// Mitsubishi GX Works2 project: L02_EIP_LIBRARY   PLC: FX3G

// task Task_01 (event TRUE, interval 0, priority 31): POU_01
// user libraries (not included): BIT_TO_INT

PROGRAM POU_01
VAR
  FB_EIP_MASTER_1 : FB_EIP_MASTER;
  FB_EIP_MASTER_2 : FB_EIP_MASTER;
  FB_EIP_MASTER_3 : FB_EIP_MASTER;
  IN_OUT_EIP_SLAVE1_1 : IN_OUT_EIP_SLAVE1;
  var1 : INT;
  vare : INT;
  BITR : BOOL;
  BITR1 : BOOL;
  BEW : BOOL;
  WE : BOOL;
  IN_OUT_EIP_SLAVE1_2 : IN_OUT_EIP_SLAVE1;
  IN_OUT_EIP_SLAVE2_1 : IN_OUT_EIP_SLAVE2;
END_VAR
(* structured ladder/FBD written out as ST: instructions are called as NAME(EN, inputs, outputs); _pN, _eN, _tN stand for wires *)
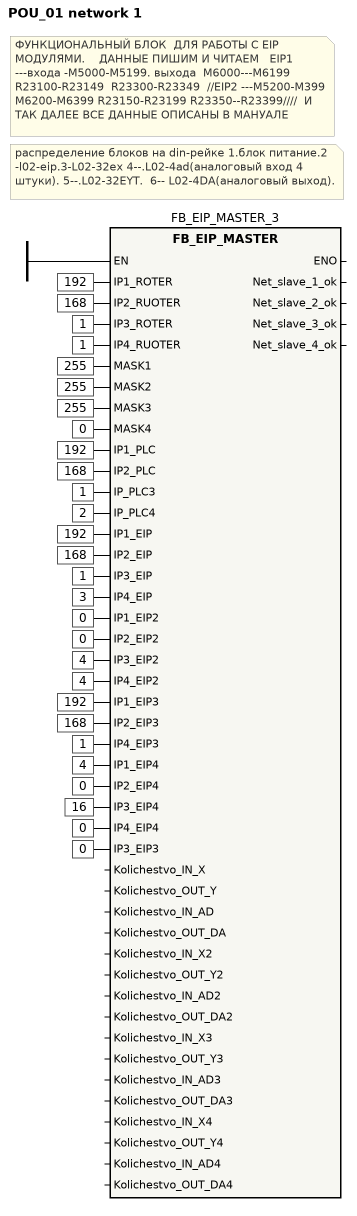
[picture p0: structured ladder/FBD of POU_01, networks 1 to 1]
(* network 1 *)
(* ФУНКЦИОНАЛЬНЫЙ БЛОК  ДЛЯ РАБОТЫ С EIP МОДУЛЯМИ.    ДАННЫЕ ПИШИМ И ЧИТАЕМ   EIP1 ---входа -М5000-М5199. выхода  M6000---M6199  R23100-R23149  R23300-R23349  //EIP2 ---M5200-M399  M6200-M6399 R23150-R23199 R23350--R23399////  И ТАК ДАЛЕЕ ВСЕ ДАННЫЕ ОПИСАНЫ В МАНУАЛЕ *)
(* распределение блоков на din-рейке 1.блок питание.2 -l02-eip.3-L02-32ex 4--.L02-4ad(аналоговый вход 4 штуки). 5--.L02-32EYT.  6-- L02-4DA(аналоговый выход). *)
FB_EIP_MASTER_3(EN := TRUE, IP1_ROTER := 192, IP2_RUOTER := 168, IP3_ROTER := 1, IP4_RUOTER := 1, MASK1 := 255, MASK2 := 255, MASK3 := 255, MASK4 := 0, IP1_PLC := 192, IP2_PLC := 168, IP_PLC3 := 1, IP_PLC4 := 2, IP1_EIP := 192, IP2_EIP := 168, IP3_EIP := 1, IP4_EIP := 3, IP1_EIP2 := 0, IP2_EIP2 := 0, IP3_EIP2 := 4, IP4_EIP2 := 4, IP1_EIP3 := 192, IP2_EIP3 := 168, IP4_EIP3 := 1, IP1_EIP4 := 4, IP2_EIP4 := 0, IP3_EIP4 := 16, IP4_EIP4 := 0, IP3_EIP3 := 0);
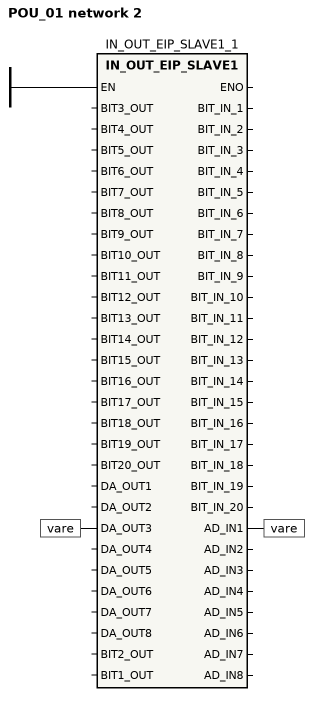
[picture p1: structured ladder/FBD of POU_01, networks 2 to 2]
(* network 2 *)
IN_OUT_EIP_SLAVE1_1(EN := TRUE, DA_OUT3 := vare, AD_IN1 => vare);
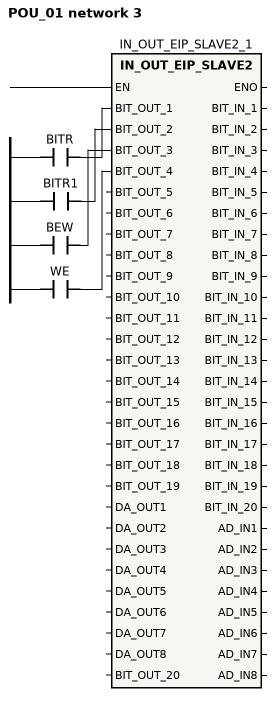
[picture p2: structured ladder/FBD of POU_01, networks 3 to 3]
(* network 3 *)
IN_OUT_EIP_SLAVE2_1(EN := TRUE, BIT_OUT_1 := BITR, BIT_OUT_2 := BITR1, BIT_OUT_3 := BEW, BIT_OUT_4 := WE);
END_PROGRAM

FUNCTION_BLOCK FB_EIP_MASTER
VAR_INPUT
  IP1_ROTER : INT;
  IP2_RUOTER : INT;
  IP3_ROTER : INT;
  IP4_RUOTER : INT;
  MASK1 : INT;
  MASK2 : INT;
  MASK3 : INT;
  MASK4 : INT;
  IP1_PLC : INT;
  IP2_PLC : INT;
  IP_PLC3 : INT;
  IP_PLC4 : INT;
  IP1_EIP : INT;
  IP2_EIP : INT;
  IP3_EIP : INT;
  IP4_EIP : INT;
  IP1_EIP2 : INT;
  IP2_EIP2 : INT;
  IP3_EIP2 : INT;
  IP4_EIP2 : INT;
  IP1_EIP3 : INT;
  IP2_EIP3 : INT;
  IP4_EIP3 : INT;
  IP1_EIP4 : INT;
  IP2_EIP4 : INT;
  IP3_EIP4 : INT;
  IP4_EIP4 : INT;
  IP3_EIP3 : INT;
  Kolichestvo_IN_X : INT;
  Kolichestvo_OUT_Y : INT;
  Kolichestvo_IN_AD : INT;
  Kolichestvo_OUT_DA : INT;
  Kolichestvo_IN_X2 : INT;
  Kolichestvo_OUT_Y2 : INT;
  Kolichestvo_IN_AD2 : INT;
  Kolichestvo_OUT_DA2 : INT;
  Kolichestvo_IN_X3 : INT;
  Kolichestvo_OUT_Y3 : INT;
  Kolichestvo_IN_AD3 : INT;
  Kolichestvo_OUT_DA3 : INT;
  Kolichestvo_IN_X4 : INT;
  Kolichestvo_OUT_Y4 : INT;
  Kolichestvo_IN_AD4 : INT;
  Kolichestvo_OUT_DA4 : INT;
END_VAR
VAR_OUTPUT
  Net_slave_1_ok : BOOL;
  Net_slave_2_ok : BOOL;
  Net_slave_3_ok : BOOL;
  Net_slave_4_ok : BOOL;
END_VAR
(* structured ladder/FBD written out as ST: instructions are called as NAME(EN, inputs, outputs); _pN, _eN, _tN stand for wires *)
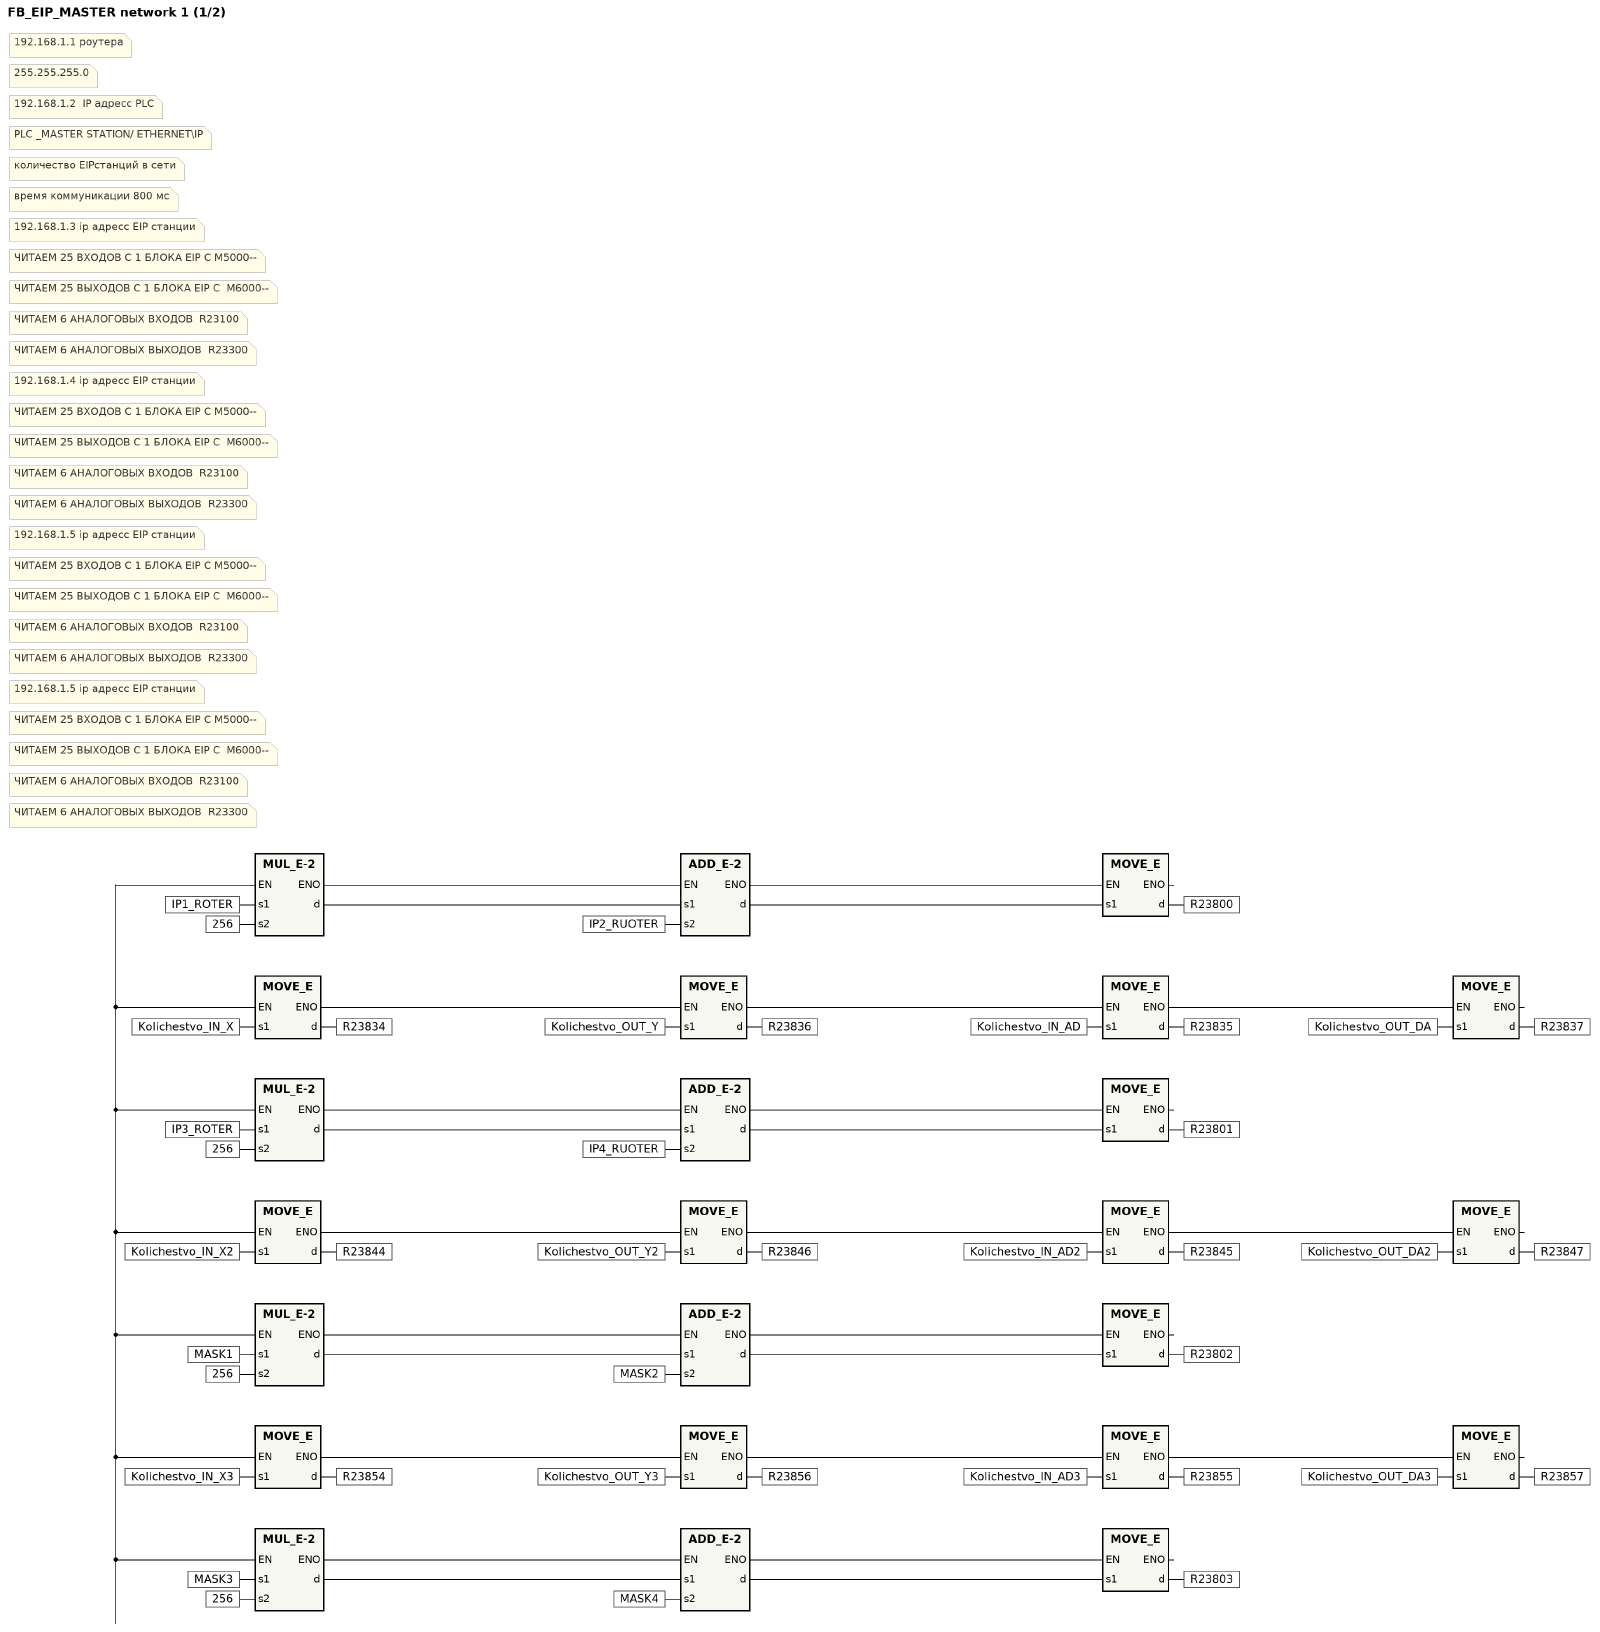
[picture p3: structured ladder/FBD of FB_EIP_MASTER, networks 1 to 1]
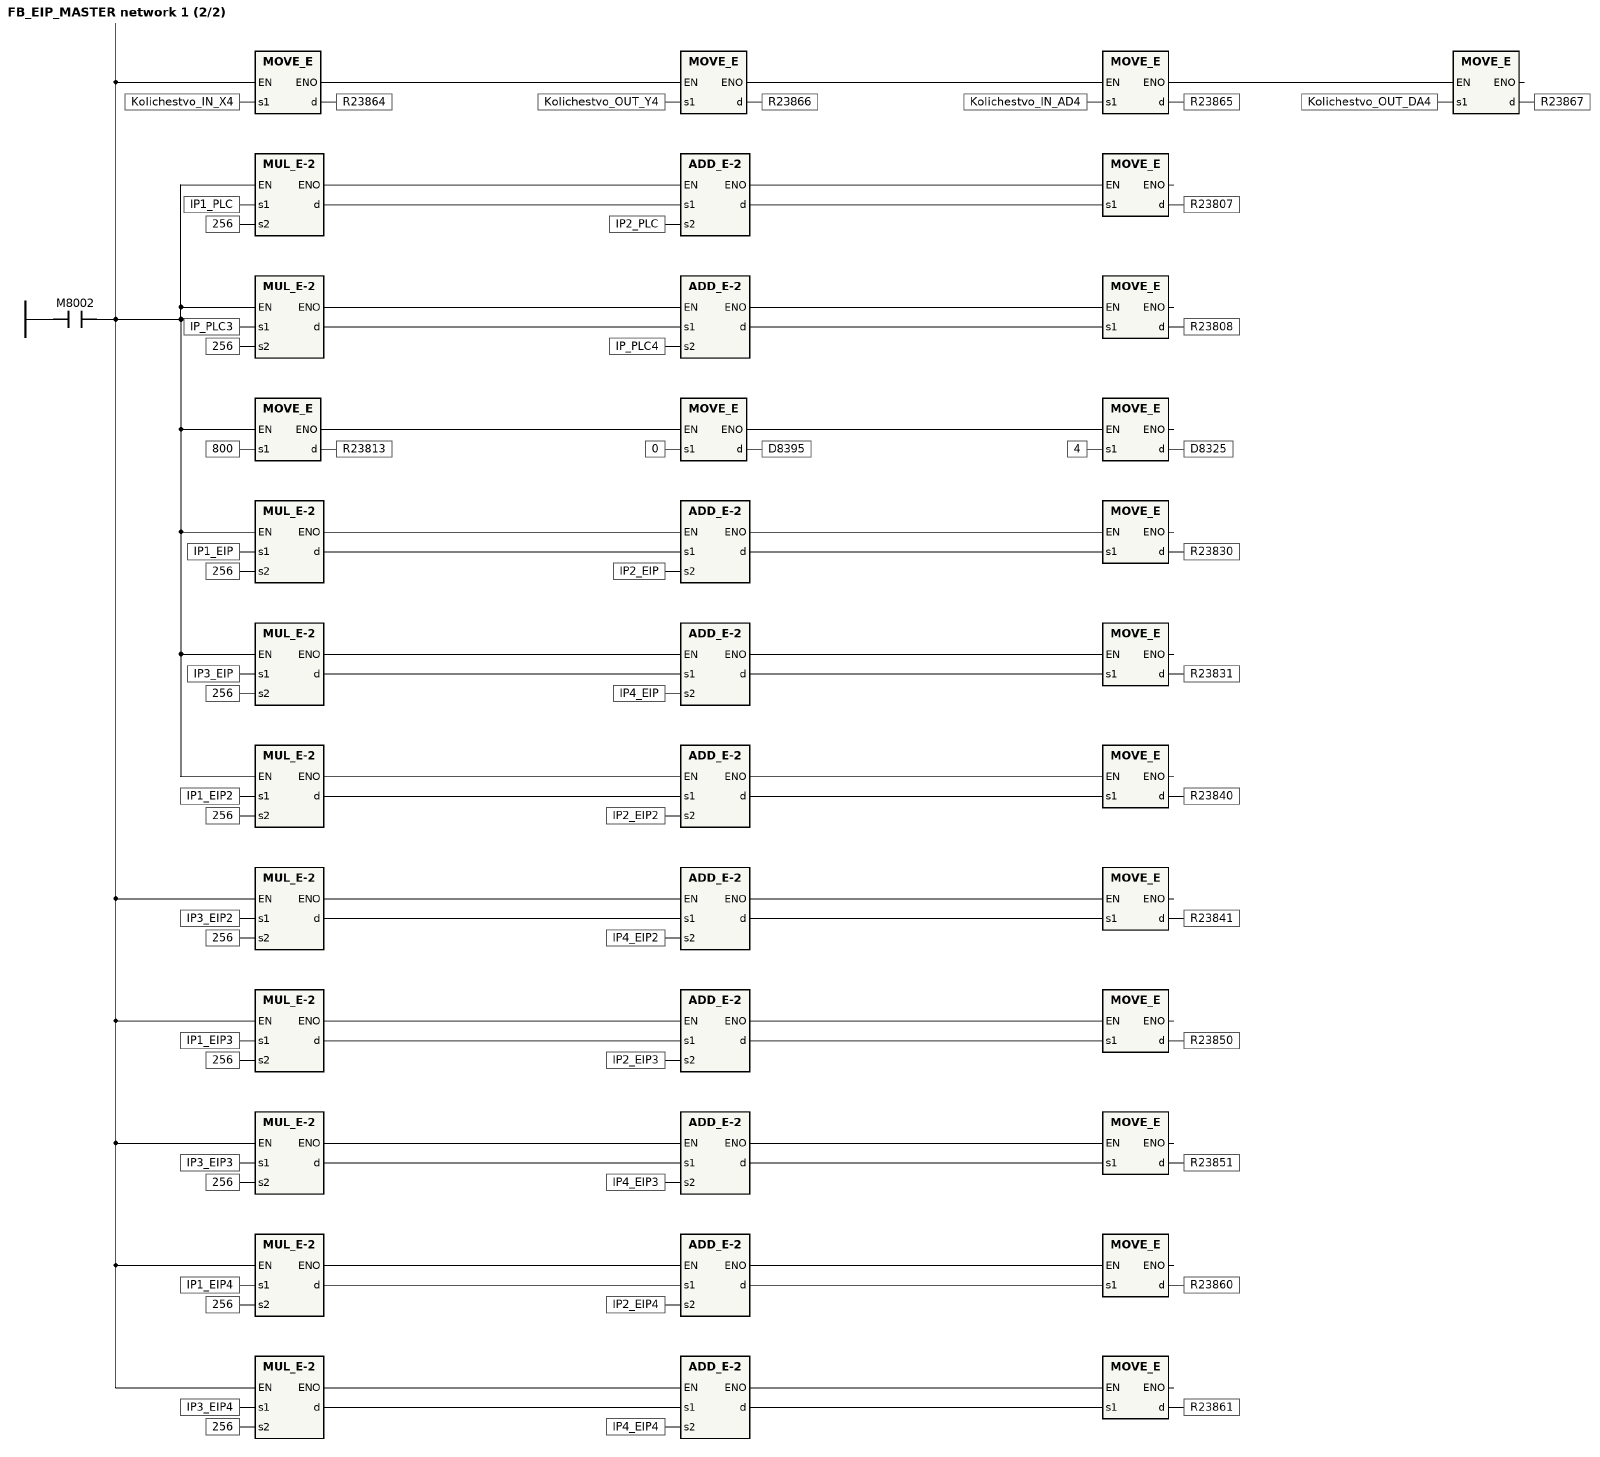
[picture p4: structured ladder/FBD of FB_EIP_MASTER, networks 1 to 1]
(* network 1 *)
(* 192.168.1.1 роутера *)
(* 255.255.255.0 *)
(* 192.168.1.2  IP адресс PLC *)
(* PLC _MASTER STATION/ ETHERNET\IP *)
(* количество EIPстанций в сети *)
(* время коммуникации 800 мс *)
(* 192.168.1.3 ip адресс EIP станции *)
(* ЧИТАЕМ 25 ВХОДОВ С 1 БЛОКА EIP C M5000-- *)
(* ЧИТАЕМ 25 ВЫХОДОВ С 1 БЛОКА EIP C  M6000-- *)
(* ЧИТАЕМ 6 АНАЛОГОВЫХ ВХОДОВ  R23100 *)
(* ЧИТАЕМ 6 АНАЛОГОВЫХ ВЫХОДОВ  R23300 *)
(* 192.168.1.4 ip адресс EIP станции *)
(* ЧИТАЕМ 25 ВХОДОВ С 1 БЛОКА EIP C M5000-- *)
(* ЧИТАЕМ 25 ВЫХОДОВ С 1 БЛОКА EIP C  M6000-- *)
(* ЧИТАЕМ 6 АНАЛОГОВЫХ ВХОДОВ  R23100 *)
(* ЧИТАЕМ 6 АНАЛОГОВЫХ ВЫХОДОВ  R23300 *)
(* 192.168.1.5 ip адресс EIP станции *)
(* ЧИТАЕМ 25 ВХОДОВ С 1 БЛОКА EIP C M5000-- *)
(* ЧИТАЕМ 25 ВЫХОДОВ С 1 БЛОКА EIP C  M6000-- *)
(* ЧИТАЕМ 6 АНАЛОГОВЫХ ВХОДОВ  R23100 *)
(* ЧИТАЕМ 6 АНАЛОГОВЫХ ВЫХОДОВ  R23300 *)
(* 192.168.1.5 ip адресс EIP станции *)
(* ЧИТАЕМ 25 ВХОДОВ С 1 БЛОКА EIP C M5000-- *)
(* ЧИТАЕМ 25 ВЫХОДОВ С 1 БЛОКА EIP C  M6000-- *)
(* ЧИТАЕМ 6 АНАЛОГОВЫХ ВХОДОВ  R23100 *)
(* ЧИТАЕМ 6 АНАЛОГОВЫХ ВЫХОДОВ  R23300 *)
_e2 := MUL_E(M8002, IP1_ROTER, 256, _t1);
_e4 := ADD_E(_e2, _t1, IP2_RUOTER, _t3);
MOVE_E(_e4, _t3, R23800);
_e6 := MUL_E(M8002, IP3_ROTER, 256, _t5);
_e8 := ADD_E(_e6, _t5, IP4_RUOTER, _t7);
MOVE_E(_e8, _t7, R23801);
_e10 := MUL_E(M8002, MASK1, 256, _t9);
_e12 := ADD_E(_e10, _t9, MASK2, _t11);
MOVE_E(_e12, _t11, R23802);
_e14 := MUL_E(M8002, MASK3, 256, _t13);
_e16 := ADD_E(_e14, _t13, MASK4, _t15);
MOVE_E(_e16, _t15, R23803);
_e18 := MUL_E(M8002, IP1_PLC, 256, _t17);
_e20 := ADD_E(_e18, _t17, IP2_PLC, _t19);
MOVE_E(_e20, _t19, R23807);
_e22 := MUL_E(M8002, IP_PLC3, 256, _t21);
_e24 := ADD_E(_e22, _t21, IP_PLC4, _t23);
MOVE_E(_e24, _t23, R23808);
_e25 := MOVE_E(M8002, 800, R23813);
_e26 := MOVE_E(_e25, 0, D8395);
MOVE_E(_e26, 4, D8325);
_e28 := MUL_E(M8002, IP1_EIP, 256, _t27);
_e30 := ADD_E(_e28, _t27, IP2_EIP, _t29);
MOVE_E(_e30, _t29, R23830);
_e32 := MUL_E(M8002, IP3_EIP, 256, _t31);
_e34 := ADD_E(_e32, _t31, IP4_EIP, _t33);
MOVE_E(_e34, _t33, R23831);
_e35 := MOVE_E(M8002, Kolichestvo_IN_X, R23834);
_e36 := MOVE_E(_e35, Kolichestvo_OUT_Y, R23836);
_e37 := MOVE_E(_e36, Kolichestvo_IN_AD, R23835);
MOVE_E(_e37, Kolichestvo_OUT_DA, R23837);
_e39 := MUL_E(M8002, IP1_EIP2, 256, _t38);
_e41 := ADD_E(_e39, _t38, IP2_EIP2, _t40);
MOVE_E(_e41, _t40, R23840);
_e43 := MUL_E(M8002, IP3_EIP2, 256, _t42);
_e45 := ADD_E(_e43, _t42, IP4_EIP2, _t44);
MOVE_E(_e45, _t44, R23841);
_e46 := MOVE_E(M8002, Kolichestvo_IN_X2, R23844);
_e47 := MOVE_E(_e46, Kolichestvo_OUT_Y2, R23846);
_e48 := MOVE_E(_e47, Kolichestvo_IN_AD2, R23845);
MOVE_E(_e48, Kolichestvo_OUT_DA2, R23847);
_e50 := MUL_E(M8002, IP1_EIP3, 256, _t49);
_e52 := ADD_E(_e50, _t49, IP2_EIP3, _t51);
MOVE_E(_e52, _t51, R23850);
_e54 := MUL_E(M8002, IP3_EIP3, 256, _t53);
_e56 := ADD_E(_e54, _t53, IP4_EIP3, _t55);
MOVE_E(_e56, _t55, R23851);
_e57 := MOVE_E(M8002, Kolichestvo_IN_X3, R23854);
_e58 := MOVE_E(_e57, Kolichestvo_OUT_Y3, R23856);
_e59 := MOVE_E(_e58, Kolichestvo_IN_AD3, R23855);
MOVE_E(_e59, Kolichestvo_OUT_DA3, R23857);
_e61 := MUL_E(M8002, IP1_EIP4, 256, _t60);
_e63 := ADD_E(_e61, _t60, IP2_EIP4, _t62);
MOVE_E(_e63, _t62, R23860);
_e65 := MUL_E(M8002, IP3_EIP4, 256, _t64);
_e67 := ADD_E(_e65, _t64, IP4_EIP4, _t66);
MOVE_E(_e67, _t66, R23861);
_e68 := MOVE_E(M8002, Kolichestvo_IN_X4, R23864);
_e69 := MOVE_E(_e68, Kolichestvo_OUT_Y4, R23866);
_e70 := MOVE_E(_e69, Kolichestvo_IN_AD4, R23865);
MOVE_E(_e70, Kolichestvo_OUT_DA4, R23867);
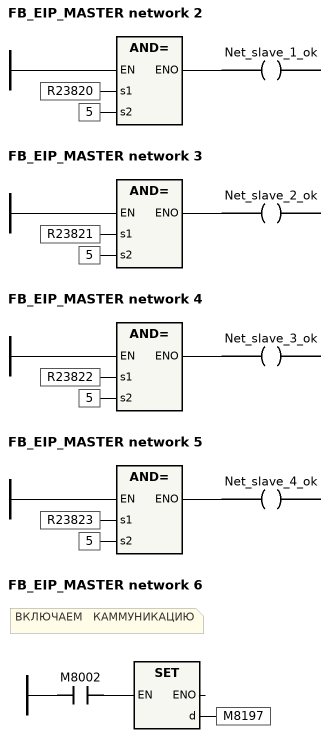
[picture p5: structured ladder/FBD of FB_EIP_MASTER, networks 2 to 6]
(* network 2 *)
_e1 := AND=(TRUE, R23820, 5);
Net_slave_1_ok := _e1;
(* network 3 *)
_e1 := AND=(TRUE, R23821, 5);
Net_slave_2_ok := _e1;
(* network 4 *)
_e1 := AND=(TRUE, R23822, 5);
Net_slave_3_ok := _e1;
(* network 5 *)
_e1 := AND=(TRUE, R23823, 5);
Net_slave_4_ok := _e1;
(* network 6 *)
(* ВКЛЮЧАЕМ   КАММУНИКАЦИЮ *)
SET(M8002, M8197);
END_FUNCTION_BLOCK

FUNCTION_BLOCK IN_OUT_EIP_SLAVE1
VAR_INPUT
  BIT3_OUT : BOOL;
  BIT4_OUT : BOOL;
  BIT5_OUT : BOOL;
  BIT6_OUT : BOOL;
  BIT7_OUT : BOOL;
  BIT8_OUT : BOOL;
  BIT9_OUT : BOOL;
  BIT10_OUT : BOOL;
  BIT11_OUT : BOOL;
  BIT12_OUT : BOOL;
  BIT13_OUT : BOOL;
  BIT14_OUT : BOOL;
  BIT15_OUT : BOOL;
  BIT16_OUT : BOOL;
  BIT17_OUT : BOOL;
  BIT18_OUT : BOOL;
  BIT19_OUT : BOOL;
  BIT20_OUT : BOOL;
END_VAR
VAR_OUTPUT
  BIT_IN_1 : BOOL;
  BIT_IN_2 : BOOL;
  BIT_IN_3 : BOOL;
  BIT_IN_4 : BOOL;
  BIT_IN_5 : BOOL;
  BIT_IN_6 : BOOL;
  BIT_IN_7 : BOOL;
  BIT_IN_8 : BOOL;
  BIT_IN_9 : BOOL;
  BIT_IN_10 : BOOL;
  BIT_IN_11 : BOOL;
  BIT_IN_12 : BOOL;
  BIT_IN_13 : BOOL;
  BIT_IN_14 : BOOL;
  BIT_IN_15 : BOOL;
  BIT_IN_16 : BOOL;
  BIT_IN_17 : BOOL;
  BIT_IN_18 : BOOL;
  BIT_IN_19 : BOOL;
  BIT_IN_20 : BOOL;
  AD_IN1 : INT;
  AD_IN2 : INT;
  AD_IN3 : INT;
  AD_IN4 : INT;
  AD_IN5 : INT;
  AD_IN6 : INT;
  AD_IN7 : INT;
  AD_IN8 : INT;
END_VAR
VAR_INPUT
  DA_OUT1 : INT;
  DA_OUT2 : INT;
  DA_OUT3 : INT;
  DA_OUT4 : INT;
  DA_OUT5 : INT;
  DA_OUT6 : INT;
  DA_OUT7 : INT;
  DA_OUT8 : INT;
  BIT2_OUT : BOOL;
  BIT1_OUT : BOOL;
END_VAR
(* structured ladder/FBD written out as ST: instructions are called as NAME(EN, inputs, outputs); _pN, _eN, _tN stand for wires *)
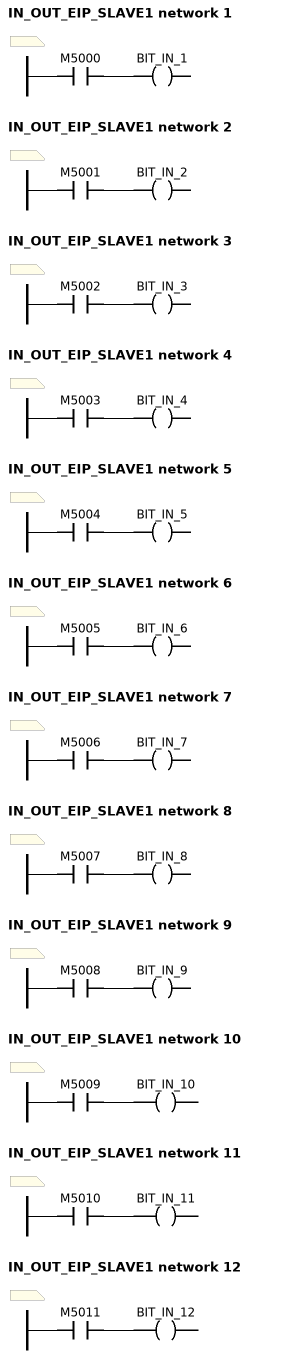
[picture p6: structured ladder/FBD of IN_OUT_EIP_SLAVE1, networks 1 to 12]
(* network 1 *)
(*  *)
BIT_IN_1 := M5000;
(* network 2 *)
(*  *)
BIT_IN_2 := M5001;
(* network 3 *)
(*  *)
BIT_IN_3 := M5002;
(* network 4 *)
(*  *)
BIT_IN_4 := M5003;
(* network 5 *)
(*  *)
BIT_IN_5 := M5004;
(* network 6 *)
(*  *)
BIT_IN_6 := M5005;
(* network 7 *)
(*  *)
BIT_IN_7 := M5006;
(* network 8 *)
(*  *)
BIT_IN_8 := M5007;
(* network 9 *)
(*  *)
BIT_IN_9 := M5008;
(* network 10 *)
(*  *)
BIT_IN_10 := M5009;
(* network 11 *)
(*  *)
BIT_IN_11 := M5010;
(* network 12 *)
(*  *)
BIT_IN_12 := M5011;
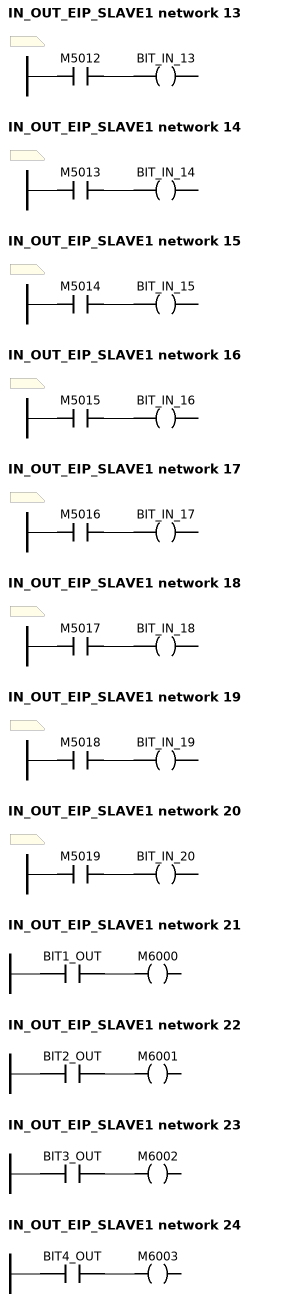
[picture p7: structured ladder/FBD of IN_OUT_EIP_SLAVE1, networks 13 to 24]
(* network 13 *)
(*  *)
BIT_IN_13 := M5012;
(* network 14 *)
(*  *)
BIT_IN_14 := M5013;
(* network 15 *)
(*  *)
BIT_IN_15 := M5014;
(* network 16 *)
(*  *)
BIT_IN_16 := M5015;
(* network 17 *)
(*  *)
BIT_IN_17 := M5016;
(* network 18 *)
(*  *)
BIT_IN_18 := M5017;
(* network 19 *)
(*  *)
BIT_IN_19 := M5018;
(* network 20 *)
(*  *)
BIT_IN_20 := M5019;
(* network 21 *)
M6000 := BIT1_OUT;
(* network 22 *)
M6001 := BIT2_OUT;
(* network 23 *)
M6002 := BIT3_OUT;
(* network 24 *)
M6003 := BIT4_OUT;
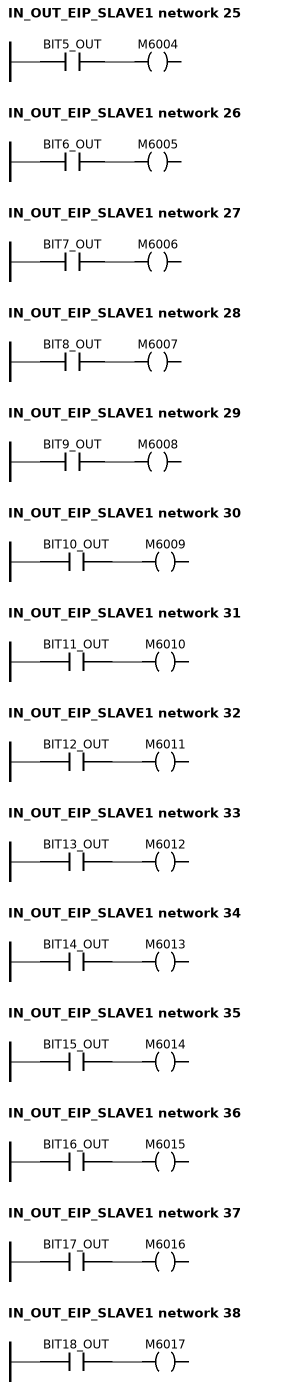
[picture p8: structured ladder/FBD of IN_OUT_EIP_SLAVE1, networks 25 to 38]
(* network 25 *)
M6004 := BIT5_OUT;
(* network 26 *)
M6005 := BIT6_OUT;
(* network 27 *)
M6006 := BIT7_OUT;
(* network 28 *)
M6007 := BIT8_OUT;
(* network 29 *)
M6008 := BIT9_OUT;
(* network 30 *)
M6009 := BIT10_OUT;
(* network 31 *)
M6010 := BIT11_OUT;
(* network 32 *)
M6011 := BIT12_OUT;
(* network 33 *)
M6012 := BIT13_OUT;
(* network 34 *)
M6013 := BIT14_OUT;
(* network 35 *)
M6014 := BIT15_OUT;
(* network 36 *)
M6015 := BIT16_OUT;
(* network 37 *)
M6016 := BIT17_OUT;
(* network 38 *)
M6017 := BIT18_OUT;
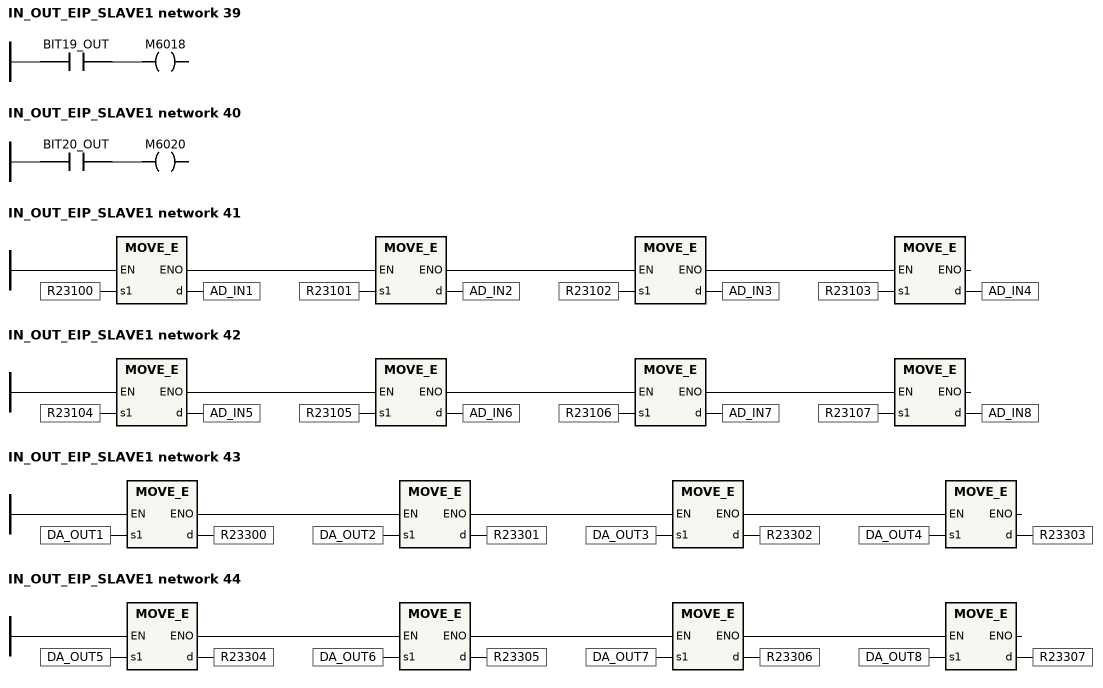
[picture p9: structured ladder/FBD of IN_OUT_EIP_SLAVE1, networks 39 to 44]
(* network 39 *)
M6018 := BIT19_OUT;
(* network 40 *)
M6020 := BIT20_OUT;
(* network 41 *)
_e1 := MOVE_E(TRUE, R23100, AD_IN1);
_e2 := MOVE_E(_e1, R23101, AD_IN2);
_e3 := MOVE_E(_e2, R23102, AD_IN3);
MOVE_E(_e3, R23103, AD_IN4);
(* network 42 *)
_e1 := MOVE_E(TRUE, R23104, AD_IN5);
_e2 := MOVE_E(_e1, R23105, AD_IN6);
_e3 := MOVE_E(_e2, R23106, AD_IN7);
MOVE_E(_e3, R23107, AD_IN8);
(* network 43 *)
_e1 := MOVE_E(TRUE, DA_OUT1, R23300);
_e2 := MOVE_E(_e1, DA_OUT2, R23301);
_e3 := MOVE_E(_e2, DA_OUT3, R23302);
MOVE_E(_e3, DA_OUT4, R23303);
(* network 44 *)
_e1 := MOVE_E(TRUE, DA_OUT5, R23304);
_e2 := MOVE_E(_e1, DA_OUT6, R23305);
_e3 := MOVE_E(_e2, DA_OUT7, R23306);
MOVE_E(_e3, DA_OUT8, R23307);
END_FUNCTION_BLOCK

FUNCTION_BLOCK IN_OUT_EIP_SLAVE2
VAR_INPUT
  BIT_OUT_1 : BOOL;
  BIT_OUT_2 : BOOL;
  BIT_OUT_3 : BOOL;
  BIT_OUT_4 : BOOL;
  BIT_OUT_5 : BOOL;
  BIT_OUT_6 : BOOL;
  BIT_OUT_7 : BOOL;
  BIT_OUT_8 : BOOL;
  BIT_OUT_9 : BOOL;
  BIT_OUT_10 : BOOL;
  BIT_OUT_11 : BOOL;
  BIT_OUT_12 : BOOL;
  BIT_OUT_13 : BOOL;
  BIT_OUT_14 : BOOL;
  BIT_OUT_15 : BOOL;
  BIT_OUT_16 : BOOL;
  BIT_OUT_17 : BOOL;
  BIT_OUT_18 : BOOL;
  BIT_OUT_19 : BOOL;
END_VAR
VAR_OUTPUT
  BIT_IN_1 : BOOL;
  BIT_IN_2 : BOOL;
  BIT_IN_3 : BOOL;
  BIT_IN_4 : BOOL;
  BIT_IN_5 : BOOL;
  BIT_IN_6 : BOOL;
  BIT_IN_7 : BOOL;
  BIT_IN_8 : BOOL;
  BIT_IN_9 : BOOL;
  BIT_IN_10 : BOOL;
  BIT_IN_11 : BOOL;
  BIT_IN_12 : BOOL;
  BIT_IN_13 : BOOL;
  BIT_IN_14 : BOOL;
  BIT_IN_15 : BOOL;
  BIT_IN_16 : BOOL;
  BIT_IN_17 : BOOL;
  BIT_IN_18 : BOOL;
  BIT_IN_19 : BOOL;
  BIT_IN_20 : BOOL;
  AD_IN1 : INT;
  AD_IN2 : INT;
  AD_IN3 : INT;
  AD_IN4 : INT;
  AD_IN5 : INT;
  AD_IN6 : INT;
  AD_IN7 : INT;
  AD_IN8 : INT;
END_VAR
VAR_INPUT
  DA_OUT1 : INT;
  DA_OUT2 : INT;
  DA_OUT3 : INT;
  DA_OUT4 : INT;
  DA_OUT5 : INT;
  DA_OUT6 : INT;
  DA_OUT7 : INT;
  DA_OUT8 : INT;
  BIT_OUT_20 : BOOL;
END_VAR
(* structured ladder/FBD written out as ST: instructions are called as NAME(EN, inputs, outputs); _pN, _eN, _tN stand for wires *)
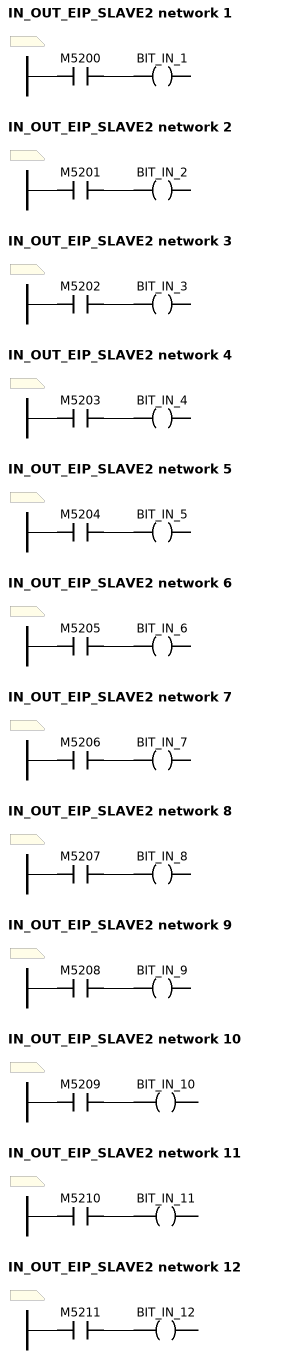
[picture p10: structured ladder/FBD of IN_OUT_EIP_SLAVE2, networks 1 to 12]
(* network 1 *)
(*  *)
BIT_IN_1 := M5200;
(* network 2 *)
(*  *)
BIT_IN_2 := M5201;
(* network 3 *)
(*  *)
BIT_IN_3 := M5202;
(* network 4 *)
(*  *)
BIT_IN_4 := M5203;
(* network 5 *)
(*  *)
BIT_IN_5 := M5204;
(* network 6 *)
(*  *)
BIT_IN_6 := M5205;
(* network 7 *)
(*  *)
BIT_IN_7 := M5206;
(* network 8 *)
(*  *)
BIT_IN_8 := M5207;
(* network 9 *)
(*  *)
BIT_IN_9 := M5208;
(* network 10 *)
(*  *)
BIT_IN_10 := M5209;
(* network 11 *)
(*  *)
BIT_IN_11 := M5210;
(* network 12 *)
(*  *)
BIT_IN_12 := M5211;
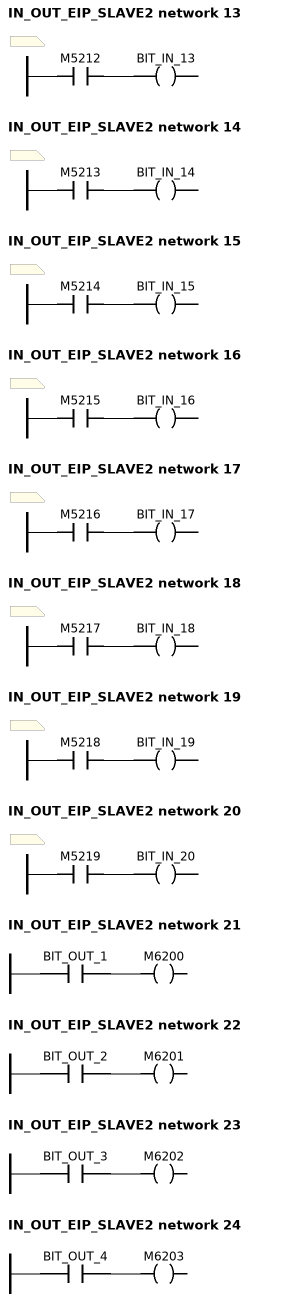
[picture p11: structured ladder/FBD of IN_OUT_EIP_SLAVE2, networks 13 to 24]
(* network 13 *)
(*  *)
BIT_IN_13 := M5212;
(* network 14 *)
(*  *)
BIT_IN_14 := M5213;
(* network 15 *)
(*  *)
BIT_IN_15 := M5214;
(* network 16 *)
(*  *)
BIT_IN_16 := M5215;
(* network 17 *)
(*  *)
BIT_IN_17 := M5216;
(* network 18 *)
(*  *)
BIT_IN_18 := M5217;
(* network 19 *)
(*  *)
BIT_IN_19 := M5218;
(* network 20 *)
(*  *)
BIT_IN_20 := M5219;
(* network 21 *)
M6200 := BIT_OUT_1;
(* network 22 *)
M6201 := BIT_OUT_2;
(* network 23 *)
M6202 := BIT_OUT_3;
(* network 24 *)
M6203 := BIT_OUT_4;
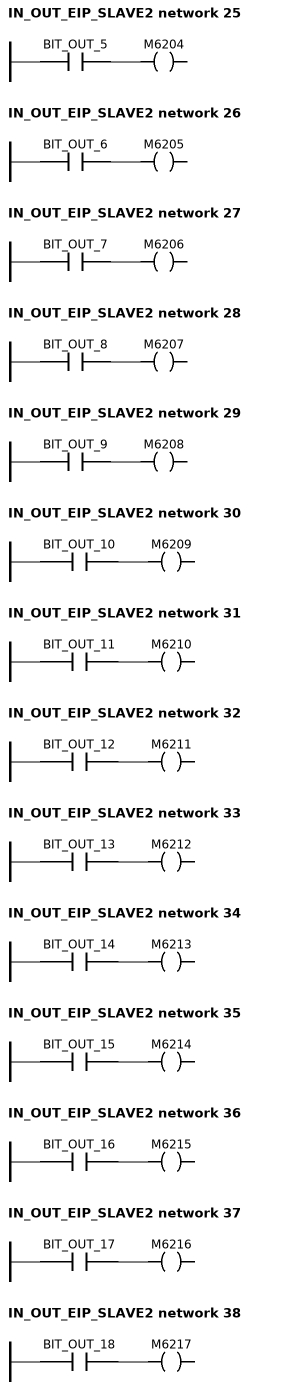
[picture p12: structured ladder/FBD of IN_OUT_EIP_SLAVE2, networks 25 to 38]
(* network 25 *)
M6204 := BIT_OUT_5;
(* network 26 *)
M6205 := BIT_OUT_6;
(* network 27 *)
M6206 := BIT_OUT_7;
(* network 28 *)
M6207 := BIT_OUT_8;
(* network 29 *)
M6208 := BIT_OUT_9;
(* network 30 *)
M6209 := BIT_OUT_10;
(* network 31 *)
M6210 := BIT_OUT_11;
(* network 32 *)
M6211 := BIT_OUT_12;
(* network 33 *)
M6212 := BIT_OUT_13;
(* network 34 *)
M6213 := BIT_OUT_14;
(* network 35 *)
M6214 := BIT_OUT_15;
(* network 36 *)
M6215 := BIT_OUT_16;
(* network 37 *)
M6216 := BIT_OUT_17;
(* network 38 *)
M6217 := BIT_OUT_18;
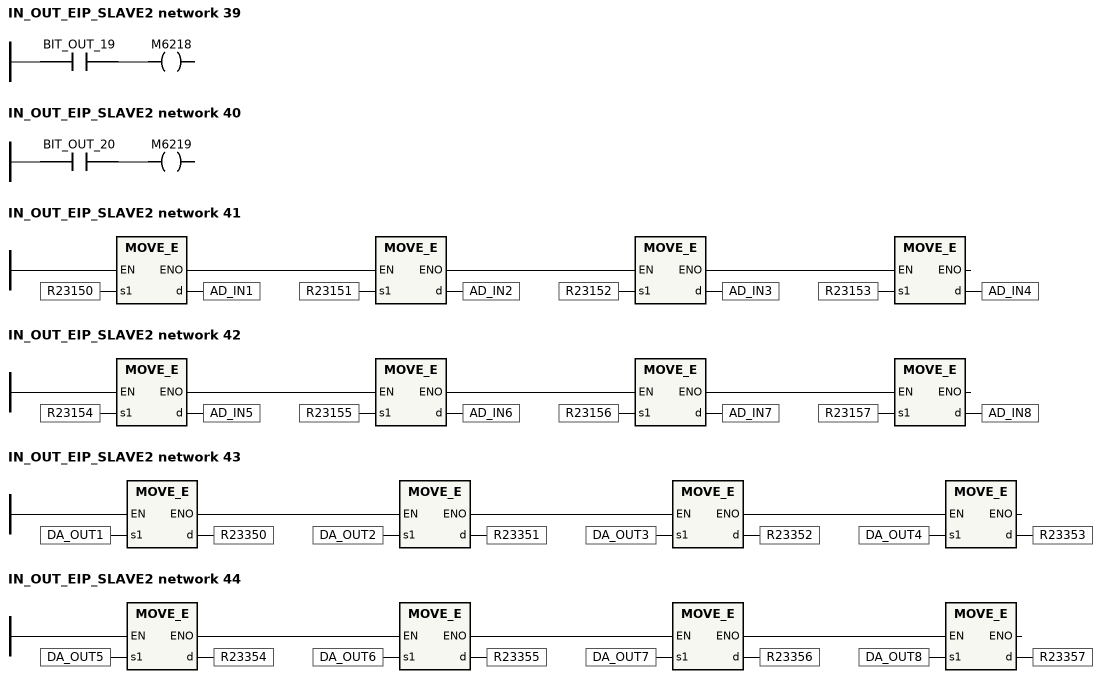
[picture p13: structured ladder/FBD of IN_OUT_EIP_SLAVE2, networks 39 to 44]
(* network 39 *)
M6218 := BIT_OUT_19;
(* network 40 *)
M6219 := BIT_OUT_20;
(* network 41 *)
_e1 := MOVE_E(TRUE, R23150, AD_IN1);
_e2 := MOVE_E(_e1, R23151, AD_IN2);
_e3 := MOVE_E(_e2, R23152, AD_IN3);
MOVE_E(_e3, R23153, AD_IN4);
(* network 42 *)
_e1 := MOVE_E(TRUE, R23154, AD_IN5);
_e2 := MOVE_E(_e1, R23155, AD_IN6);
_e3 := MOVE_E(_e2, R23156, AD_IN7);
MOVE_E(_e3, R23157, AD_IN8);
(* network 43 *)
_e1 := MOVE_E(TRUE, DA_OUT1, R23350);
_e2 := MOVE_E(_e1, DA_OUT2, R23351);
_e3 := MOVE_E(_e2, DA_OUT3, R23352);
MOVE_E(_e3, DA_OUT4, R23353);
(* network 44 *)
_e1 := MOVE_E(TRUE, DA_OUT5, R23354);
_e2 := MOVE_E(_e1, DA_OUT6, R23355);
_e3 := MOVE_E(_e2, DA_OUT7, R23356);
MOVE_E(_e3, DA_OUT8, R23357);
(*  *)
END_FUNCTION_BLOCK

FUNCTION_BLOCK IN_OUT_EIP_SLAVE3
VAR_INPUT
  BIT1_OUT : BOOL;
  BIT2_OUT : BOOL;
  BIT3_OUT : BOOL;
  BIT4_OUT : BOOL;
  BIT5_OUT : BOOL;
  BIT6_OUT : BOOL;
  BIT7_OUT : BOOL;
  BIT8_OUT : BOOL;
  BIT9_OUT : BOOL;
  BIT10_OUT : BOOL;
  BIT11_OUT : BOOL;
  BIT12_OUT : BOOL;
  BIT13_OUT : BOOL;
  BIT14_OUT : BOOL;
  BIT15_OUT : BOOL;
  BIT16_OUT : BOOL;
  BIT17_OUT : BOOL;
  BIT18_OUT : BOOL;
  BIT19_OUT : BOOL;
  BIT20_OUT : BOOL;
END_VAR
VAR_OUTPUT
  BIT_IN_1 : BOOL;
  BIT_IN_2 : BOOL;
  BIT_IN_3 : BOOL;
  BIT_IN_4 : BOOL;
  BIT_IN_5 : BOOL;
  BIT_IN_6 : BOOL;
  BIT_IN_7 : BOOL;
  BIT_IN_8 : BOOL;
  BIT_IN_9 : BOOL;
  BIT_IN_10 : BOOL;
  BIT_IN_11 : BOOL;
  BIT_IN_12 : BOOL;
  BIT_IN_13 : BOOL;
  BIT_IN_14 : BOOL;
  BIT_IN_15 : BOOL;
  BIT_IN_16 : BOOL;
  BIT_IN_17 : BOOL;
  BIT_IN_18 : BOOL;
  BIT_IN_19 : BOOL;
  BIT_IN_20 : BOOL;
  AD_IN1 : INT;
  AD_IN2 : INT;
  AD_IN3 : INT;
  AD_IN4 : INT;
  AD_IN5 : INT;
  AD_IN6 : INT;
  AD_IN7 : INT;
  AD_IN8 : INT;
END_VAR
VAR_INPUT
  DA_OUT1 : INT;
  DA_OUT2 : INT;
  DA_OUT3 : INT;
  DA_OUT4 : INT;
  DA_OUT5 : INT;
  DA_OUT6 : INT;
  DA_OUT7 : INT;
  DA_OUT8 : INT;
END_VAR
(* structured ladder/FBD written out as ST: instructions are called as NAME(EN, inputs, outputs); _pN, _eN, _tN stand for wires *)
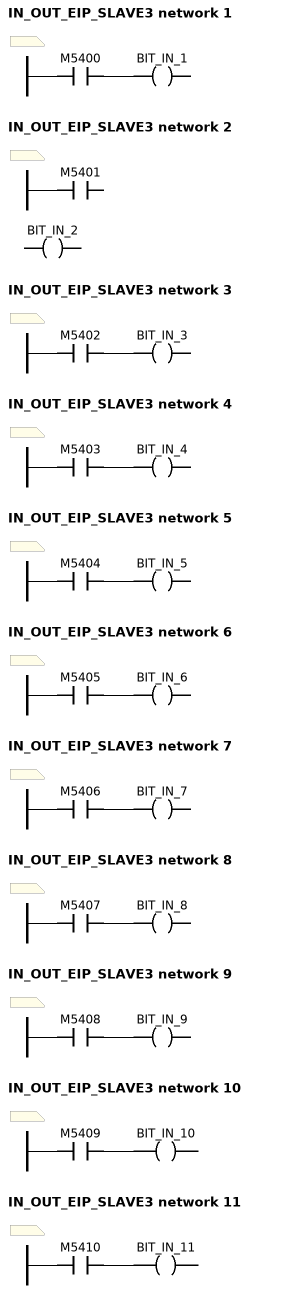
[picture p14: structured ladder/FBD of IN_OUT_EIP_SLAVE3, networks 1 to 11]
(* network 1 *)
(*  *)
BIT_IN_1 := M5400;
(* network 2 *)
(*  *)
BIT_IN_2 := FALSE;
(* not connected to any output: M5401 *)
(* network 3 *)
(*  *)
BIT_IN_3 := M5402;
(* network 4 *)
(*  *)
BIT_IN_4 := M5403;
(* network 5 *)
(*  *)
BIT_IN_5 := M5404;
(* network 6 *)
(*  *)
BIT_IN_6 := M5405;
(* network 7 *)
(*  *)
BIT_IN_7 := M5406;
(* network 8 *)
(*  *)
BIT_IN_8 := M5407;
(* network 9 *)
(*  *)
BIT_IN_9 := M5408;
(* network 10 *)
(*  *)
BIT_IN_10 := M5409;
(* network 11 *)
(*  *)
BIT_IN_11 := M5410;
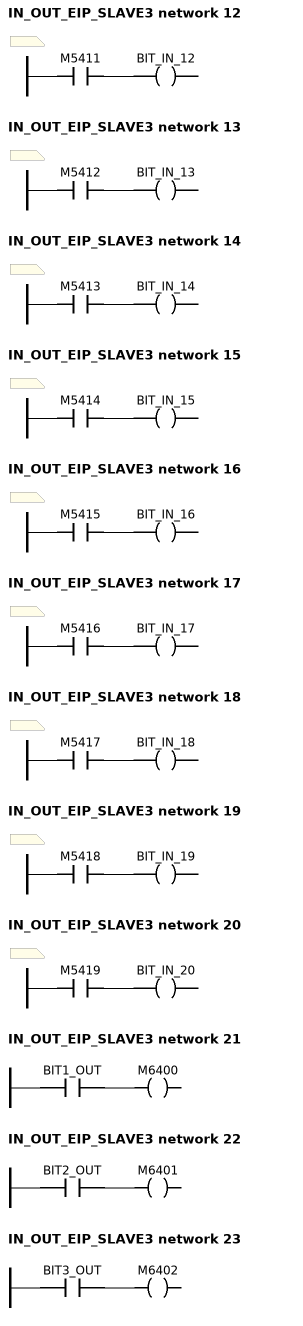
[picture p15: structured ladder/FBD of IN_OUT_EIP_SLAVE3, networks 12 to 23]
(* network 12 *)
(*  *)
BIT_IN_12 := M5411;
(* network 13 *)
(*  *)
BIT_IN_13 := M5412;
(* network 14 *)
(*  *)
BIT_IN_14 := M5413;
(* network 15 *)
(*  *)
BIT_IN_15 := M5414;
(* network 16 *)
(*  *)
BIT_IN_16 := M5415;
(* network 17 *)
(*  *)
BIT_IN_17 := M5416;
(* network 18 *)
(*  *)
BIT_IN_18 := M5417;
(* network 19 *)
(*  *)
BIT_IN_19 := M5418;
(* network 20 *)
(*  *)
BIT_IN_20 := M5419;
(* network 21 *)
M6400 := BIT1_OUT;
(* network 22 *)
M6401 := BIT2_OUT;
(* network 23 *)
M6402 := BIT3_OUT;
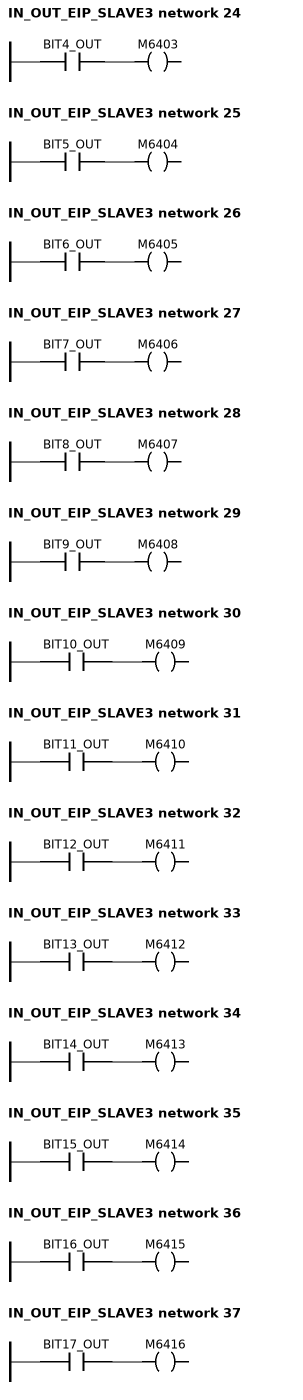
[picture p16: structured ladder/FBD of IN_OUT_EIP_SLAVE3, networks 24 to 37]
(* network 24 *)
M6403 := BIT4_OUT;
(* network 25 *)
M6404 := BIT5_OUT;
(* network 26 *)
M6405 := BIT6_OUT;
(* network 27 *)
M6406 := BIT7_OUT;
(* network 28 *)
M6407 := BIT8_OUT;
(* network 29 *)
M6408 := BIT9_OUT;
(* network 30 *)
M6409 := BIT10_OUT;
(* network 31 *)
M6410 := BIT11_OUT;
(* network 32 *)
M6411 := BIT12_OUT;
(* network 33 *)
M6412 := BIT13_OUT;
(* network 34 *)
M6413 := BIT14_OUT;
(* network 35 *)
M6414 := BIT15_OUT;
(* network 36 *)
M6415 := BIT16_OUT;
(* network 37 *)
M6416 := BIT17_OUT;
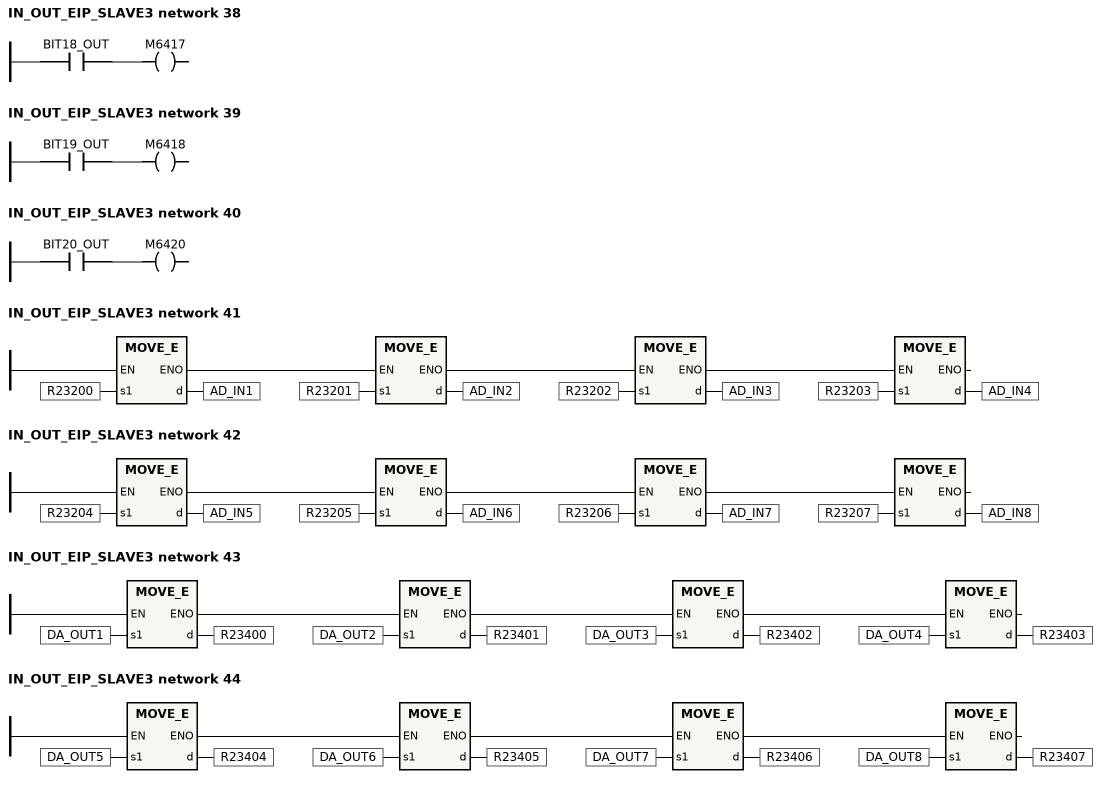
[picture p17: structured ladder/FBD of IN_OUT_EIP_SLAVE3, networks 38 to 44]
(* network 38 *)
M6417 := BIT18_OUT;
(* network 39 *)
M6418 := BIT19_OUT;
(* network 40 *)
M6420 := BIT20_OUT;
(* network 41 *)
_e1 := MOVE_E(TRUE, R23200, AD_IN1);
_e2 := MOVE_E(_e1, R23201, AD_IN2);
_e3 := MOVE_E(_e2, R23202, AD_IN3);
MOVE_E(_e3, R23203, AD_IN4);
(* network 42 *)
_e1 := MOVE_E(TRUE, R23204, AD_IN5);
_e2 := MOVE_E(_e1, R23205, AD_IN6);
_e3 := MOVE_E(_e2, R23206, AD_IN7);
MOVE_E(_e3, R23207, AD_IN8);
(* network 43 *)
_e1 := MOVE_E(TRUE, DA_OUT1, R23400);
_e2 := MOVE_E(_e1, DA_OUT2, R23401);
_e3 := MOVE_E(_e2, DA_OUT3, R23402);
MOVE_E(_e3, DA_OUT4, R23403);
(* network 44 *)
_e1 := MOVE_E(TRUE, DA_OUT5, R23404);
_e2 := MOVE_E(_e1, DA_OUT6, R23405);
_e3 := MOVE_E(_e2, DA_OUT7, R23406);
MOVE_E(_e3, DA_OUT8, R23407);
(*  *)
END_FUNCTION_BLOCK

FUNCTION_BLOCK IN_OUT_EIP_SLAVE4
VAR_INPUT
  BIT1_OUT : BOOL;
  BIT2_OUT : BOOL;
  BIT3_OUT : BOOL;
  BIT4_OUT : BOOL;
  BIT5_OUT : BOOL;
  BIT6_OUT : BOOL;
  BIT7_OUT : BOOL;
  BIT8_OUT : BOOL;
  BIT9_OUT : BOOL;
  BIT10_OUT : BOOL;
  BIT11_OUT : BOOL;
  BIT12_OUT : BOOL;
  BIT13_OUT : BOOL;
  BIT14_OUT : BOOL;
  BIT15_OUT : BOOL;
  BIT16_OUT : BOOL;
  BIT17_OUT : BOOL;
  BIT18_OUT : BOOL;
  BIT19_OUT : BOOL;
  BIT20_OUT : BOOL;
END_VAR
VAR_OUTPUT
  BIT_IN_1 : BOOL;
  BIT_IN_2 : BOOL;
  BIT_IN_3 : BOOL;
  BIT_IN_4 : BOOL;
  BIT_IN_5 : BOOL;
  BIT_IN_6 : BOOL;
  BIT_IN_7 : BOOL;
  BIT_IN_8 : BOOL;
  BIT_IN_9 : BOOL;
  BIT_IN_10 : BOOL;
  BIT_IN_11 : BOOL;
  BIT_IN_12 : BOOL;
  BIT_IN_13 : BOOL;
  BIT_IN_14 : BOOL;
  BIT_IN_15 : BOOL;
  BIT_IN_16 : BOOL;
  BIT_IN_17 : BOOL;
  BIT_IN_18 : BOOL;
  BIT_IN_19 : BOOL;
  BIT_IN_20 : BOOL;
  AD_IN1 : INT;
  AD_IN2 : INT;
  AD_IN3 : INT;
  AD_IN4 : INT;
  AD_IN5 : INT;
  AD_IN6 : INT;
  AD_IN7 : INT;
  AD_IN8 : INT;
END_VAR
VAR_INPUT
  DA_OUT1 : INT;
  DA_OUT2 : INT;
  DA_OUT3 : INT;
  DA_OUT4 : INT;
  DA_OUT5 : INT;
  DA_OUT6 : INT;
  DA_OUT7 : INT;
  DA_OUT8 : INT;
END_VAR
(* structured ladder/FBD written out as ST: instructions are called as NAME(EN, inputs, outputs); _pN, _eN, _tN stand for wires *)
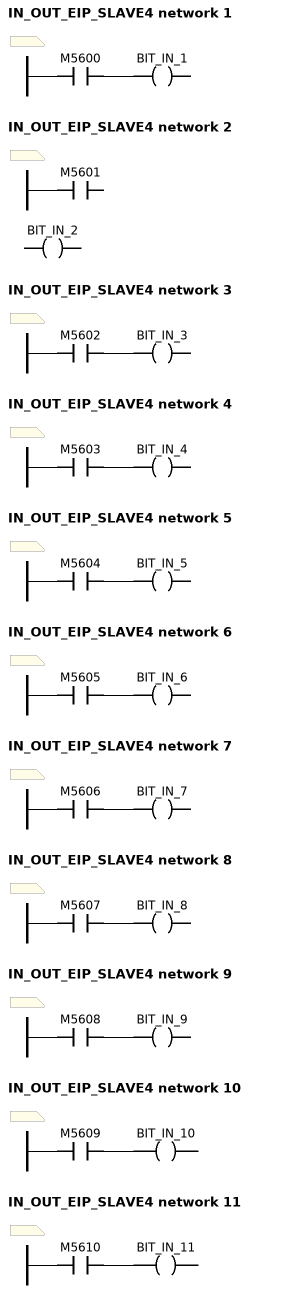
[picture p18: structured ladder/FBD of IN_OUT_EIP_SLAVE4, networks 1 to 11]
(* network 1 *)
(*  *)
BIT_IN_1 := M5600;
(* network 2 *)
(*  *)
BIT_IN_2 := FALSE;
(* not connected to any output: M5601 *)
(* network 3 *)
(*  *)
BIT_IN_3 := M5602;
(* network 4 *)
(*  *)
BIT_IN_4 := M5603;
(* network 5 *)
(*  *)
BIT_IN_5 := M5604;
(* network 6 *)
(*  *)
BIT_IN_6 := M5605;
(* network 7 *)
(*  *)
BIT_IN_7 := M5606;
(* network 8 *)
(*  *)
BIT_IN_8 := M5607;
(* network 9 *)
(*  *)
BIT_IN_9 := M5608;
(* network 10 *)
(*  *)
BIT_IN_10 := M5609;
(* network 11 *)
(*  *)
BIT_IN_11 := M5610;
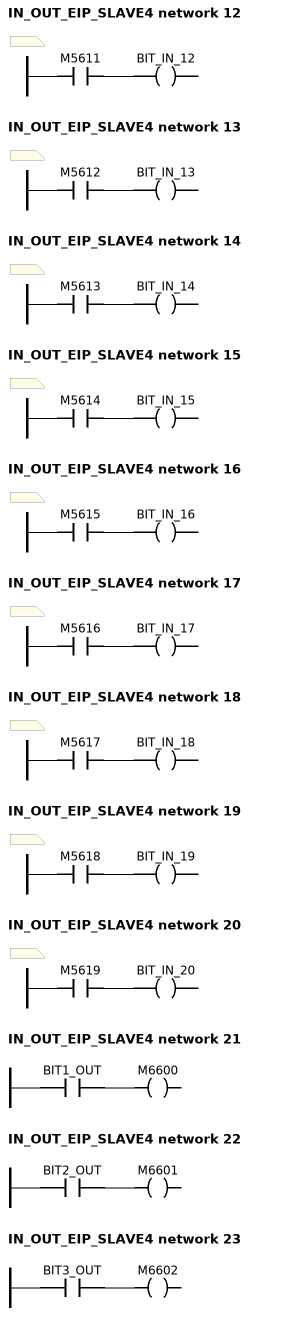
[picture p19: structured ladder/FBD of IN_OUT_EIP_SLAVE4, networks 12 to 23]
(* network 12 *)
(*  *)
BIT_IN_12 := M5611;
(* network 13 *)
(*  *)
BIT_IN_13 := M5612;
(* network 14 *)
(*  *)
BIT_IN_14 := M5613;
(* network 15 *)
(*  *)
BIT_IN_15 := M5614;
(* network 16 *)
(*  *)
BIT_IN_16 := M5615;
(* network 17 *)
(*  *)
BIT_IN_17 := M5616;
(* network 18 *)
(*  *)
BIT_IN_18 := M5617;
(* network 19 *)
(*  *)
BIT_IN_19 := M5618;
(* network 20 *)
(*  *)
BIT_IN_20 := M5619;
(* network 21 *)
M6600 := BIT1_OUT;
(* network 22 *)
M6601 := BIT2_OUT;
(* network 23 *)
M6602 := BIT3_OUT;
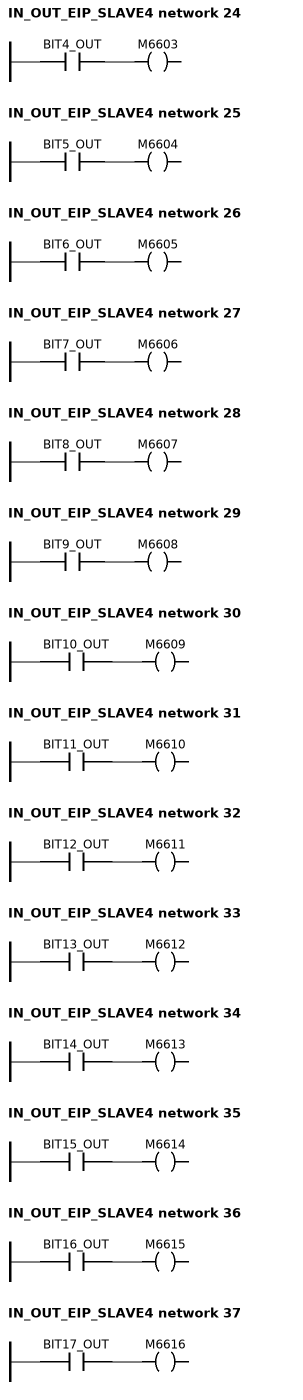
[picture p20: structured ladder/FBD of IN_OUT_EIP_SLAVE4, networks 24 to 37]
(* network 24 *)
M6603 := BIT4_OUT;
(* network 25 *)
M6604 := BIT5_OUT;
(* network 26 *)
M6605 := BIT6_OUT;
(* network 27 *)
M6606 := BIT7_OUT;
(* network 28 *)
M6607 := BIT8_OUT;
(* network 29 *)
M6608 := BIT9_OUT;
(* network 30 *)
M6609 := BIT10_OUT;
(* network 31 *)
M6610 := BIT11_OUT;
(* network 32 *)
M6611 := BIT12_OUT;
(* network 33 *)
M6612 := BIT13_OUT;
(* network 34 *)
M6613 := BIT14_OUT;
(* network 35 *)
M6614 := BIT15_OUT;
(* network 36 *)
M6615 := BIT16_OUT;
(* network 37 *)
M6616 := BIT17_OUT;
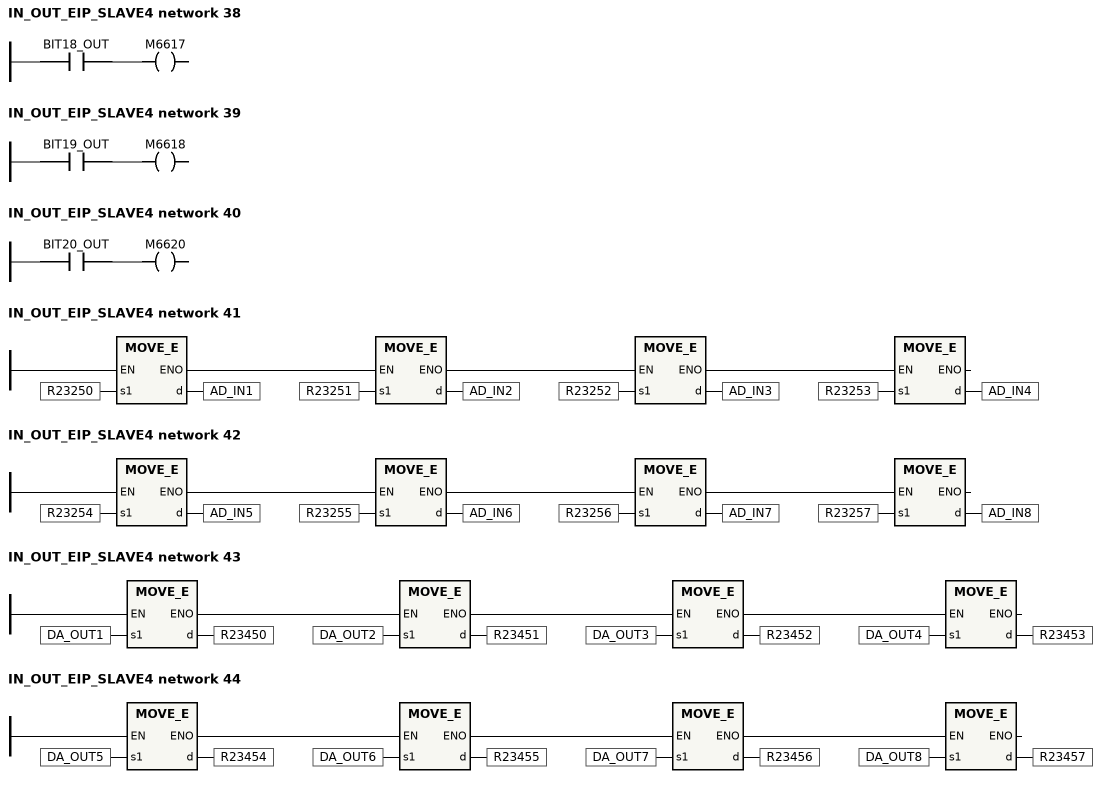
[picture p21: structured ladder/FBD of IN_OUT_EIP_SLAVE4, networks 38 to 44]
(* network 38 *)
M6617 := BIT18_OUT;
(* network 39 *)
M6618 := BIT19_OUT;
(* network 40 *)
M6620 := BIT20_OUT;
(* network 41 *)
_e1 := MOVE_E(TRUE, R23250, AD_IN1);
_e2 := MOVE_E(_e1, R23251, AD_IN2);
_e3 := MOVE_E(_e2, R23252, AD_IN3);
MOVE_E(_e3, R23253, AD_IN4);
(* network 42 *)
_e1 := MOVE_E(TRUE, R23254, AD_IN5);
_e2 := MOVE_E(_e1, R23255, AD_IN6);
_e3 := MOVE_E(_e2, R23256, AD_IN7);
MOVE_E(_e3, R23257, AD_IN8);
(* network 43 *)
_e1 := MOVE_E(TRUE, DA_OUT1, R23450);
_e2 := MOVE_E(_e1, DA_OUT2, R23451);
_e3 := MOVE_E(_e2, DA_OUT3, R23452);
MOVE_E(_e3, DA_OUT4, R23453);
(* network 44 *)
_e1 := MOVE_E(TRUE, DA_OUT5, R23454);
_e2 := MOVE_E(_e1, DA_OUT6, R23455);
_e3 := MOVE_E(_e2, DA_OUT7, R23456);
MOVE_E(_e3, DA_OUT8, R23457);
(*  *)
END_FUNCTION_BLOCK
